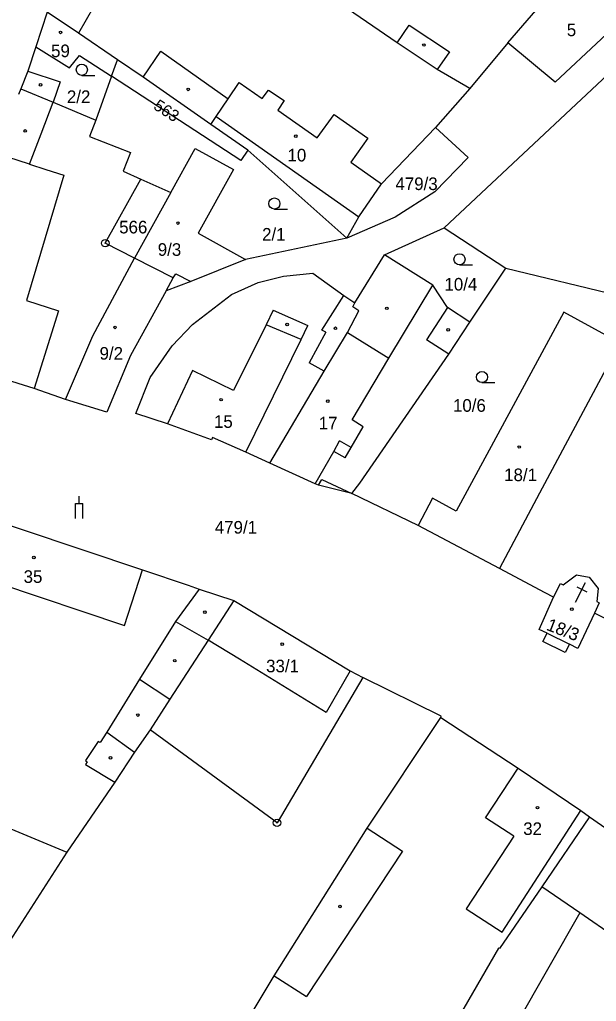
# Model space of a CAD drawing. Extents: x -758582 to -751794, y -998770 to -994350.
# Drawn here: x -756423.9 to -756346.2, y -997002.8 to -996870.6 of the extents above; entities that cross this region are included whole.
import ezdxf

# ---------------------------------------------------------------- set-up
doc = ezdxf.new("R2010")
doc.units = 0
for name, color, linetype in [('Hranice parcel', 7, 'Continuous'), ('Parcelní čísla', 7, 'Continuous'), ('Vnitřní kresba', 7, 'Continuous'), ('Značky bodu BP', 7, 'Continuous'), ('Značky budov', 7, 'Continuous'), ('Značky kultur', 7, 'Continuous')]:
    doc.layers.add(name, color=color, linetype=linetype)

msp = doc.modelspace()

# ---------------------------------------------------------------- linework, layer by layer
at = {"layer": 'Hranice parcel'}
for p, q in [((-756420.14, -996869.54), (-756421.67, -996874.21)), ((-756415.94, -996872.39), (-756420.14, -996869.54)), ((-756410.67, -996875.97), (-756415.94, -996872.39)), ((-756421.67, -996874.21), (-756422.74, -996877.49)), ((-756358.09, -996873.7), (-756363.24, -996879.83)), ((-756411.47, -996878.19), (-756410.67, -996875.97)), ((-756411.47, -996878.19), (-756413.6, -996884.09)), ((-756363.24, -996879.83), (-756367.86, -996885.11)), ((-756379.79, -996900), (-756393.1, -996888.17)), ((-756407.54, -996892.05), (-756403.49, -996893.84)), ((-756403.49, -996893.84), (-756408.37, -996902.7)), ((-756374.72, -996902.27), (-756366.67, -996898.6)), ((-756366.67, -996898.6), (-756358.37, -996904.03)), ((-756379.79, -996900), (-756393.42, -996902.88)), ((-756378.69, -996908.72), (-756374.72, -996902.27)), ((-756363.22, -996911.31), (-756358.37, -996904.03)), ((-756358.37, -996904.03), (-756334.86, -996909.75)), ((-756370.18, -996938.72), (-756379.11, -996934.43)), ((-756417.51, -996982.73), (-756432.81, -997006.39))]:
    msp.add_line(p, q, dxfattribs=at)
for points in [[(-756405.06, -996852.66), (-756411.81, -996865.14), (-756415.94, -996872.39)], [(-756363.24, -996879.83), (-756367.61, -996877.29), (-756372.99, -996873.7), (-756397.78, -996856.66), (-756405.06, -996852.66)], [(-756358.09, -996873.7), (-756351.72, -996866.26), (-756348.87, -996861.62)], [(-756339.23, -996867.27), (-756351.71, -996879.01), (-756358.09, -996873.7)], [(-756366.67, -996898.6), (-756337.54, -996871.31), (-756332.79, -996874.38)], [(-756421.67, -996874.21), (-756417.15, -996877.04), (-756415.78, -996875.38), (-756411.47, -996878.19)], [(-756393.1, -996888.17), (-756398.09, -996884.71), (-756407.22, -996878.32), (-756410.67, -996875.97)], [(-756422.74, -996877.49), (-756423.7, -996879.88), (-756424.01, -996880.63)], [(-756422.74, -996877.49), (-756418.41, -996878.95), (-756419.33, -996881.7), (-756413.6, -996884.09)], [(-756393.1, -996888.17), (-756394.05, -996889.55), (-756411.47, -996878.19)], [(-756413.6, -996884.09), (-756414.45, -996886.32), (-756408.92, -996888.48), (-756409.93, -996891), (-756407.54, -996892.05)], [(-756367.86, -996885.11), (-756363.46, -996889.12), (-756367.93, -996893.78), (-756373.26, -996897.18), (-756379.79, -996900)], [(-756379.79, -996900), (-756378.19, -996897.15), (-756375.1, -996892.71), (-756367.86, -996885.11)], [(-756403.49, -996893.84), (-756400.21, -996887.93), (-756395.05, -996890.74), (-756399.8, -996899.33), (-756393.42, -996902.88)], [(-756408.37, -996902.7), (-756412.32, -996900.68), (-756407.54, -996892.05)], [(-756417.68, -996921.73), (-756413.99, -996913.18), (-756408.37, -996902.7)], [(-756404.11, -996907.11), (-756403.17, -996905.36), (-756408.37, -996902.7)], [(-756393.42, -996902.88), (-756400.81, -996905.85), (-756404.11, -996907.11)], [(-756363.22, -996911.31), (-756366.23, -996909.35), (-756368.21, -996906.34), (-756374.72, -996902.27)], [(-756390.15, -996930.32), (-756393.4, -996928.84), (-756397.9, -996926.86), (-756398.01, -996927.19), (-756403.92, -996925.03), (-756408.2, -996923.63), (-756406.28, -996918.78), (-756403.33, -996914.53), (-756400.58, -996911.65), (-756395.32, -996907.59), (-756391.72, -996905.97), (-756388.32, -996905.12), (-756384.38, -996904.72), (-756380.17, -996907.72), (-756378.69, -996908.72)], [(-756404.11, -996907.11), (-756408.91, -996915.84), (-756412.13, -996923.44), (-756417.68, -996921.73)], [(-756390.15, -996930.32), (-756382.84, -996917.91), (-756379.72, -996912.7), (-756378.16, -996909.78), (-756379, -996909.26), (-756378.69, -996908.72)], [(-756334.86, -996909.75), (-756343.02, -996914.1), (-756350.56, -996909.98), (-756365.06, -996936.81), (-756368.25, -996935.05), (-756370.18, -996938.72)], [(-756379.11, -996934.43), (-756378.05, -996933.02), (-756366.07, -996915.65), (-756363.22, -996911.31)], [(-756417.68, -996921.73), (-756421.89, -996920.28), (-756436.73, -996915.63)], [(-756379.11, -996934.43), (-756383.59, -996933.28), (-756384.06, -996933.1), (-756390.15, -996930.32)], [(-756306.31, -996933.33), (-756319.42, -996952.02), (-756321.69, -996955.29), (-756332.12, -996957.81), (-756346.43, -996950.53)], [(-756433.65, -996941.25), (-756431.88, -996936.48), (-756407.29, -996944.71), (-756401.17, -996946.78), (-756399.68, -996947.29), (-756394.99, -996948.83)], [(-756351.94, -996948.37), (-756353.06, -996947.81), (-756359.23, -996944.53), (-756370.18, -996938.72)], [(-756351.94, -996948.37), (-756351.01, -996946.55), (-756350.66, -996946.7), (-756348.87, -996945.38), (-756347.14, -996945.67), (-756345.95, -996947.22), (-756346.11, -996948.97), (-756345.78, -996949.13), (-756346.43, -996950.53)], [(-756346.43, -996950.53), (-756348.66, -996955.3), (-756349.82, -996954.72), (-756350.38, -996955.85), (-756353.39, -996954.37), (-756352.82, -996953.25), (-756353.89, -996952.72), (-756351.94, -996948.37)], [(-756394.99, -996948.83), (-756398.45, -996954.16), (-756403.62, -996962.14), (-756406.28, -996966.24)], [(-756394.99, -996948.83), (-756379.34, -996958.32), (-756377.64, -996959.23)], [(-756377.64, -996959.23), (-756389.19, -996978.79), (-756406.28, -996966.24)], [(-756367.11, -996964.62), (-756367.06, -996964.41), (-756377.64, -996959.23)], [(-756409.91, -997034.27), (-756404.57, -997024.41), (-756389.59, -996999.41), (-756377.04, -996979.5), (-756367.11, -996964.62)], [(-756367.11, -996964.62), (-756356.69, -996971.42), (-756348.29, -996977.12), (-756347.1, -996977.98)], [(-756406.28, -996966.24), (-756408.39, -996969.26), (-756411.03, -996973.33), (-756417.51, -996982.73)], [(-756446.01, -996970.89), (-756440.95, -996973), (-756417.51, -996982.73)], [(-756347.1, -996977.98), (-756353.53, -996987.41), (-756359.21, -996995.73), (-756359.35, -996995.69), (-756369.17, -997012.71), (-756373.93, -997019.02), (-756388.2, -997038.37), (-756388.32, -997038.28), (-756393.35, -997045.03)], [(-756347.1, -996977.98), (-756343.29, -996980.63), (-756343.07, -996980.42), (-756336.17, -996985.21), (-756336.27, -996985.49), (-756332.16, -996988.42), (-756332.01, -996988.69), (-756332.1, -996988.96), (-756333.1, -996990.33), (-756326.54, -996995.14)]]:
    msp.add_lwpolyline(points, dxfattribs=at)
at = {"layer": 'Vnitřní kresba'}
for p, q in [((-756372.99, -996873.7), (-756371.41, -996871.29)), ((-756371.41, -996871.29), (-756365.98, -996874.88)), ((-756407.22, -996878.32), (-756404.82, -996874.82)), ((-756404.82, -996874.82), (-756395.78, -996881.22)), ((-756365.98, -996874.88), (-756367.61, -996877.29)), ((-756395.78, -996881.22), (-756394.3, -996879.03)), ((-756394.3, -996879.03), (-756391.17, -996881.21)), ((-756423.7, -996879.88), (-756419.33, -996881.7)), ((-756391.17, -996881.21), (-756390.32, -996880.07)), ((-756390.32, -996880.07), (-756388.24, -996881.47)), ((-756420.95, -996885.94), (-756419.33, -996881.7)), ((-756397.4, -996883.6), (-756395.78, -996881.22)), ((-756388.24, -996881.47), (-756389.1, -996882.74)), ((-756389.1, -996882.74), (-756383.79, -996886.51)), ((-756383.79, -996886.51), (-756381.49, -996883.35)), ((-756381.49, -996883.35), (-756376.98, -996886.54)), ((-756398.09, -996884.71), (-756397.4, -996883.6)), ((-756397.4, -996883.6), (-756378.19, -996897.15)), ((-756422.52, -996890.04), (-756420.95, -996885.94)), ((-756376.98, -996886.54), (-756379.26, -996889.78)), ((-756422.52, -996890.04), (-756427.03, -996888.61)), ((-756422.52, -996890.04), (-756420.32, -996890.74)), ((-756379.26, -996889.78), (-756375.1, -996892.71)), ((-756420.32, -996890.74), (-756417.89, -996891.51)), ((-756417.89, -996891.51), (-756422.93, -996908.42)), ((-756403.17, -996905.36), (-756402.84, -996904.82)), ((-756402.84, -996904.82), (-756400.81, -996905.85)), ((-756374.14, -996916.17), (-756368.21, -996906.34)), ((-756422.93, -996908.42), (-756418.61, -996909.81)), ((-756383.17, -996912.39), (-756380.17, -996907.72)), ((-756418.61, -996909.81), (-756421.89, -996920.28)), ((-756389.73, -996909.72), (-756390.63, -996911.68)), ((-756389.73, -996909.72), (-756385.04, -996911.77)), ((-756366.23, -996909.35), (-756369.06, -996913.73)), ((-756390.63, -996911.68), (-756395.05, -996920.54)), ((-756385.96, -996913.65), (-756390.63, -996911.68)), ((-756385.96, -996913.65), (-756385.04, -996911.77)), ((-756382.62, -996912.66), (-756384.87, -996916.8)), ((-756382.62, -996912.66), (-756383.17, -996912.39)), ((-756393.4, -996928.84), (-756385.96, -996913.65)), ((-756379.72, -996912.7), (-756374.14, -996916.17)), ((-756366.07, -996915.65), (-756369.06, -996913.73)), ((-756343.02, -996914.1), (-756353.82, -996934.37)), ((-756379.07, -996924.5), (-756374.14, -996916.17)), ((-756400.57, -996917.86), (-756403.92, -996925.03)), ((-756395.05, -996920.54), (-756400.57, -996917.86)), ((-756382.84, -996917.91), (-756384.87, -996916.8)), ((-756377.59, -996925.42), (-756379.07, -996924.5)), ((-756379.2, -996928.21), (-756377.59, -996925.42)), ((-756381.56, -996928.75), (-756380.77, -996927.32)), ((-756379.2, -996928.21), (-756380.77, -996927.32)), ((-756380.02, -996929.62), (-756379.2, -996928.21)), ((-756384.06, -996933.1), (-756381.56, -996928.75)), ((-756380.02, -996929.62), (-756381.56, -996928.75)), ((-756383.59, -996933.28), (-756383.17, -996932.51)), ((-756383.17, -996932.51), (-756379.11, -996934.43)), ((-756353.82, -996934.37), (-756359.23, -996944.53)), ((-756429.02, -996945.71), (-756409.73, -996952.2)), ((-756409.73, -996952.2), (-756407.29, -996944.71)), ((-756399.68, -996947.29), (-756402.85, -996951.65)), ((-756402.85, -996951.65), (-756407.69, -996959.45)), ((-756402.85, -996951.65), (-756398.45, -996954.16)), ((-756352.82, -996953.25), (-756349.82, -996954.72)), ((-756394.24, -996956.75), (-756398.45, -996954.16)), ((-756382.59, -996963.91), (-756394.24, -996956.75)), ((-756379.34, -996958.32), (-756382.59, -996963.91)), ((-756407.69, -996959.45), (-756412.11, -996966.58)), ((-756407.69, -996959.45), (-756403.62, -996962.14)), ((-756412.11, -996966.58), (-756413.01, -996967.97)), ((-756412.11, -996966.58), (-756408.39, -996969.26)), ((-756413.28, -996967.84), (-756414.99, -996970.41)), ((-756413.01, -996967.97), (-756413.28, -996967.84)), ((-756414.76, -996970.57), (-756415, -996970.93)), ((-756414.99, -996970.41), (-756414.76, -996970.57)), ((-756415, -996970.93), (-756411.03, -996973.33)), ((-756361.13, -996978.11), (-756356.69, -996971.42)), ((-756358.88, -996993.51), (-756348.29, -996977.12)), ((-756357.3, -996980.6), (-756361.13, -996978.11)), ((-756377.04, -996979.5), (-756372.31, -996982.6)), ((-756357.3, -996980.6), (-756363.72, -996990.4)), ((-756372.31, -996982.6), (-756385.23, -997002.2)), ((-756348.4, -996990.93), (-756353.53, -996987.41)), ((-756363.72, -996990.4), (-756358.88, -996993.51)), ((-756348.4, -996990.93), (-756366.86, -997023.17)), ((-756343.58, -996994.24), (-756348.4, -996990.93)), ((-756389.59, -996999.41), (-756385.23, -997002.2))]:
    msp.add_line(p, q, dxfattribs=at)
at = {"layer": 'Značky bodu BP'}
for centre, radius in [((-756412.32, -996900.68), 0.5), ((-756412.32, -996900.68), 0.0303), ((-756389.19, -996978.79), 0.5), ((-756389.19, -996978.79), 0.0303)]:
    msp.add_circle(centre, radius, dxfattribs=at)
at = {"layer": 'Značky budov'}
for p, q in [((-756347.69, -996946.43), (-756349.05, -996949.1)), ((-756348.81, -996946.98), (-756347.47, -996947.66))]:
    msp.add_line(p, q, dxfattribs=at)
for centre in [(-756418.34, -996872.28), (-756369.4, -996873.98), (-756421.03, -996879.35), (-756401.14, -996879.96), (-756423.1, -996885.56), (-756386.67, -996886.27), (-756402.53, -996897.97), (-756374.4, -996909.46), (-756411.01, -996912.03), (-756387.84, -996911.64), (-756381.33, -996912.15), (-756366.13, -996912.35), (-756396.73, -996921.77), (-756382.36, -996921.97), (-756356.56, -996928.15), (-756421.93, -996943.04), (-756398.9, -996950.41), (-756349.48, -996950), (-756388.48, -996954.72), (-756402.97, -996956.94), (-756407.92, -996964.27), (-756411.61, -996970.03), (-756354.1, -996976.75), (-756380.71, -996990.06)]:
    msp.add_circle(centre, 0.175, dxfattribs=at)
at = {"layer": 'Značky kultur'}
for p, q in [((-756415.48, -996878.07), (-756413.73, -996878.07)), ((-756389.54, -996896.09), (-756387.79, -996896.09)), ((-756364.61, -996903.6), (-756362.86, -996903.6)), ((-756361.59, -996919.48), (-756359.84, -996919.48)), ((-756415.83, -996935.78), (-756415.83, -996934.78)), ((-756416.33, -996935.78), (-756415.33, -996935.78)), ((-756416.33, -996937.78), (-756416.33, -996935.78)), ((-756415.33, -996937.78), (-756415.33, -996935.78))]:
    msp.add_line(p, q, dxfattribs=at)
for centre in [(-756415.48, -996877.32), (-756389.54, -996895.34), (-756364.61, -996902.85), (-756361.59, -996918.73)]:
    msp.add_circle(centre, 0.75, dxfattribs=at)

# ---------------------------------------------------------------- texts
at = {"layer": 'Parcelní čísla'}
for s, p in [('5', (-756350.16, -996872.79)), ('59', (-756419.62, -996875.62)), ('2/2', (-756417.49, -996881.8)), ('10', (-756387.78, -996889.67)), ('479/3', (-756373.24, -996893.53)), ('566', (-756410.45, -996899.37)), ('2/1', (-756391.2, -996900.34)), ('9/3', (-756405.25, -996902.39)), ('10/4', (-756366.64, -996907.07)), ('9/2', (-756413.09, -996916.38)), ('10/6', (-756365.49, -996923.4)), ('15', (-756397.68, -996925.57)), ('17', (-756383.57, -996925.78)), ('18/1', (-756358.6, -996932.75)), ('479/1', (-756397.57, -996939.82)), ('35', (-756423.32, -996946.46)), ('33/1', (-756390.66, -996958.51)), ('32', (-756356.03, -996980.43))]:
    msp.add_text(s, height=1.7, dxfattribs=at).set_placement(p)
for s, height, rotation, p in [('563', 1.568, 327, (-756405.95, -996882.52)), ('18/3', 1.7, 339, (-756353.03, -996952.76))]:
    msp.add_text(s, height=height, rotation=rotation, dxfattribs=at).set_placement(p)

doc.saveas('drawing.dxf')
